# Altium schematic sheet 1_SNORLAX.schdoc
size 429 x 307 mm; Symbol: Drawing-Symbol_A4; Device: Drawing-Symbol_A4; @Project Name: Slowpoke_Adapter; @Page Count: 1; @Update Date: 2025-12-10; @Create Date: 2025-11-02; @Schematic Name: Schematic3; @Page No: 1; @Page Name: SNORLAX; Company: EasyEDA.com; Version: V1.0; Page Size: A4; @Create Time: 12:35:37; @Update Time: 15:02:42; Width: 1655; Height: 1170; Region Start: 1; X Region Count: 6; Y Region Count: 4; Blade Width: 10; Title Block Position: 3; @Board Name: SNORLAX
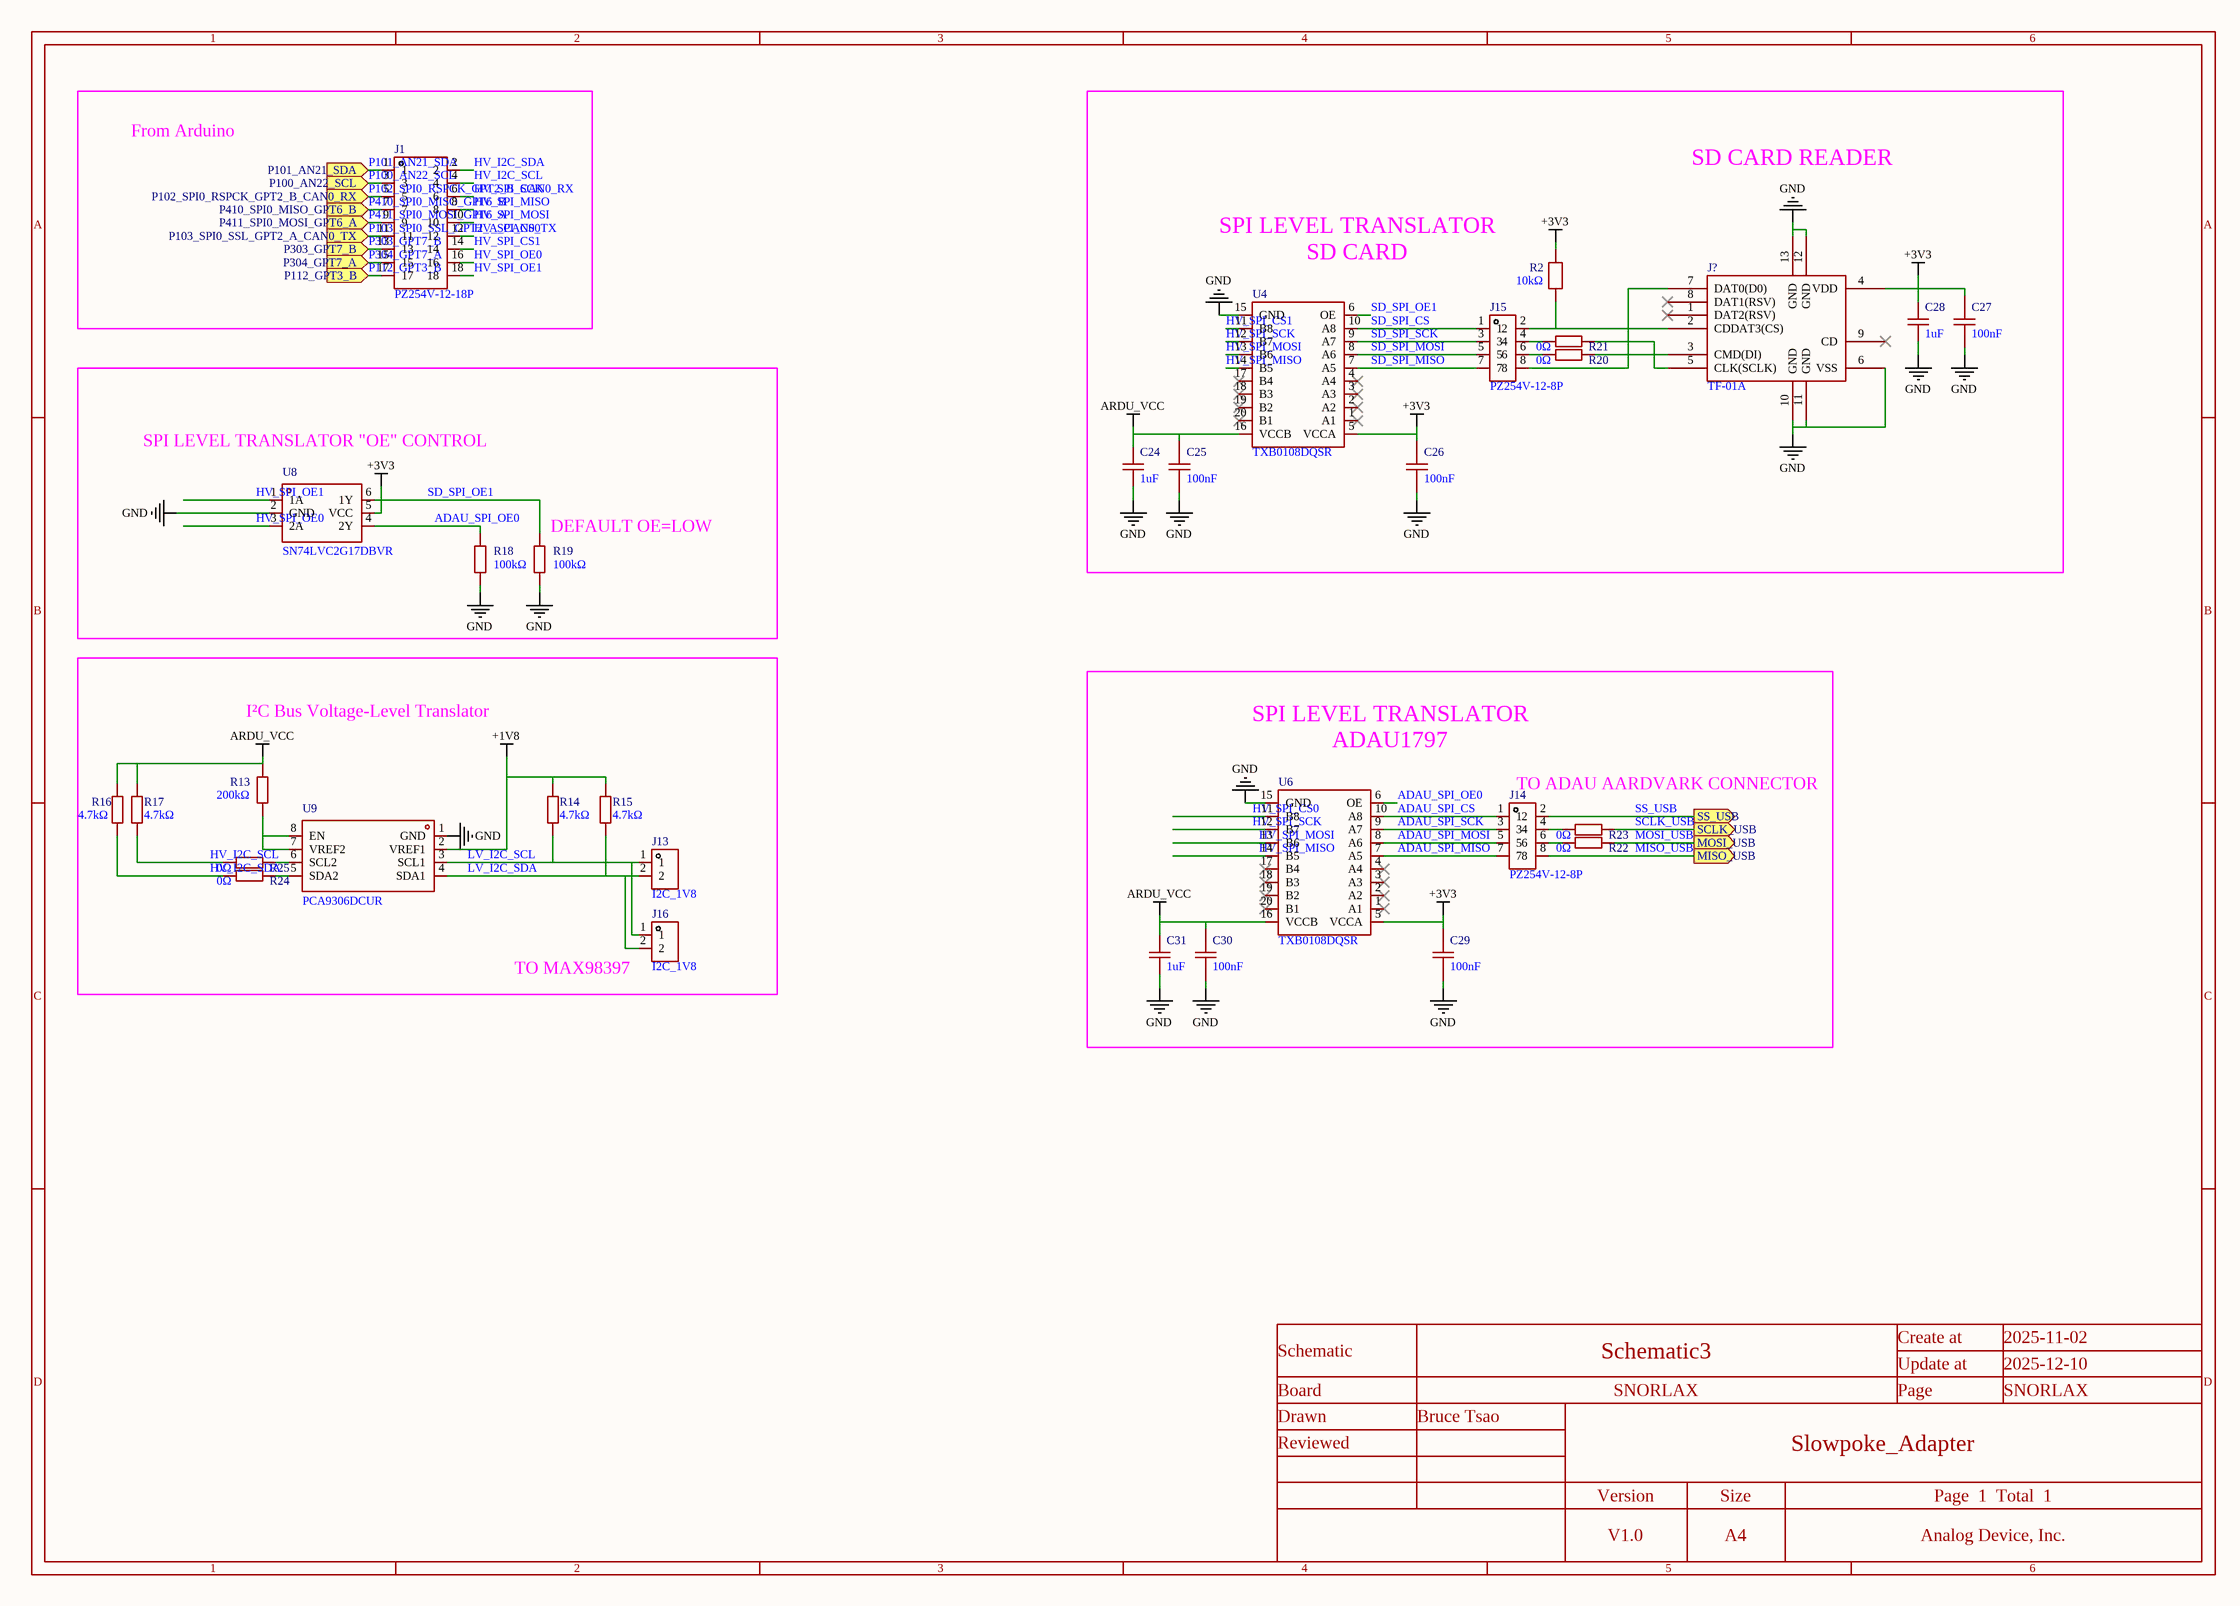
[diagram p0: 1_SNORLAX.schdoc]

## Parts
C24  1uF  [C0402]
C25  100nF  [C0402]
C26  100nF  [C0402]
C27  100nF  [C0402]
C28  1uF  [C0402]
C29  100nF  [C0402]
C30  100nF  [C0402]
C31  1uF  [C0402]
J1  PZ254V-12-18P  [HDR-TH_18P-P2.54-V-M-R2-C9-S2.54]
J13  I2C_1V8  [HDR-TH_2P-P2.54-V-M]
J14  PZ254V-12-8P  [HDR-TH_8P-P2.54-V-M-R2-C4-S2.54]
J15  PZ254V-12-8P  [HDR-TH_8P-P2.54-V-M-R2-C4-S2.54]
J16  I2C_1V8  [HDR-TH_2P-P2.54-V-M]
J?  TF-01A  [TF-SMD_TF-01A]
R2  10kΩ  [R0402]
R13  200kΩ  [R0603]
R14  4.7kΩ  [R0603]
R15  4.7kΩ  [R0603]
R16  4.7kΩ  [R0603]
R17  4.7kΩ  [R0603]
R18  100kΩ  [R0603]
R19  100kΩ  [R0603]
R20  0Ω  [R0402]
R21  0Ω  [R0402]
R22  0Ω  [R0402]
R23  0Ω  [R0402]
R24  0Ω  [R0402]
R25  0Ω  [R0402]
U4  TXB0108DQSR  [SON-20_L4.0-W2.0-P0.40-BL]
U6  TXB0108DQSR  [SON-20_L4.0-W2.0-P0.40-BL]
U8  SN74LVC2G17DBVR  [SOT-23-6_L2.9-W1.6-P0.95-LS2.8-BL]
U9  PCA9306DCUR  [SSOP-8_L2.0-W2.3-P0.50-LS3.1-BR]

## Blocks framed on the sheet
From Arduino: J1
SD CARD READER: C24-C28 J15 J? R2 R20 R21 U4
TO ADAU AARDVARK CONNECTOR: C29-C31 J14 R22 R23 U6

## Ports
MISO_USB (out), MOSI_USB (out), P100_AN22_SCL (in), P101_AN21_SDA (in), P102_SPI0_RSPCK_GPT2_B_CAN0_RX (in), P103_SPI0_SSL_GPT2_A_CAN0_TX (in), P112_GPT3_B (in), P303_GPT7_B (in), P304_GPT7_A (in), P410_SPI0_MISO_GPT6_B (in), P411_SPI0_MOSI_GPT6_A (in), SCLK_USB (out), SS_USB (out)

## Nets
+1V8: R14.2 R15.2 U9.2(VREF1)
+3V3: C26.2 C27.2 C28.2 C29.2 J?.4(VDD) R2.2 U4.5(VCCA) U6.5(VCCA) U8.5(VCC)
ARDU_VCC: C24.2 C25.2 C30.2 C31.2 R13.2 R16.2 R17.2 U4.16(VCCB) U6.16(VCCB)
GND: C24.1 C25.1 C26.1 C27.1 C28.1 C29.1 C30.1 C31.1 J?.6(VSS) J?.10(GND) J?.11(GND) J?.12(GND) J?.13(GND) R18.1 R19.1 U4.15(GND) U6.15(GND) U8.2(GND) U9.1(GND)
ADAU_SPI_CS: J14.1 U6.10(A8)
ADAU_SPI_MISO: J14.7 U6.7(A5)
ADAU_SPI_MOSI: J14.5 U6.8(A6)
ADAU_SPI_OE0: R18.2 U6.6(OE) U8.4(2Y)
ADAU_SPI_SCK: J14.3 U6.9(A7)
HV_I2C_SCL: J1.4 R17.1 R25.1
HV_I2C_SDA: J1.2 R16.1 R24.1
HV_SPI_CS0: J1.12 U6.11(B8)
HV_SPI_CS1: J1.14 U4.11(B8)
HV_SPI_MISO: J1.8 U4.14(B5) U6.14(B5)
HV_SPI_MOSI: J1.10 U4.13(B6) U6.13(B6)
HV_SPI_OE0: J1.16 U8.3(2A)
HV_SPI_OE1: J1.18 U8.1(1A)
HV_SPI_SCK: J1.6 U4.12(B7) U6.12(B7)
LV_I2C_SCL: J13.1 J16.1 R14.1 U9.3(SCL1)
LV_I2C_SDA: J13.2 J16.2 R15.1 U9.4(SDA1)
MISO_USB: J14.8 ; port MISO_USB
MOSI_USB: R22.2 ; port MOSI_USB
P100_AN22_SCL: J1.3 ; port P100_AN22_SCL
P101_AN21_SDA: J1.1 ; port P101_AN21_SDA
P102_SPI0_RSPCK_GPT2_B_CAN0_RX: J1.5 ; port P102_SPI0_RSPCK_GPT2_B_CAN0_RX
P103_SPI0_SSL_GPT2_A_CAN0_TX: J1.11 ; port P103_SPI0_SSL_GPT2_A_CAN0_TX
P112_GPT3_B: J1.17 ; port P112_GPT3_B
P303_GPT7_B: J1.13 ; port P303_GPT7_B
P304_GPT7_A: J1.15 ; port P304_GPT7_A
P410_SPI0_MISO_GPT6_B: J1.7 ; port P410_SPI0_MISO_GPT6_B
P411_SPI0_MOSI_GPT6_A: J1.9 ; port P411_SPI0_MOSI_GPT6_A
SCLK_USB: R23.2 ; port SCLK_USB
SD_SPI_CS: J15.1 U4.10(A8)
SD_SPI_MISO: J15.7 U4.7(A5)
SD_SPI_MOSI: J15.5 U4.8(A6)
SD_SPI_OE1: R19.2 U4.6(OE) U8.6(1Y)
SD_SPI_SCK: J15.3 U4.9(A7)
SS_USB: J14.2 ; port SS_USB
NetJ14_4: J14.4 R23.1
NetJ14_6: J14.6 R22.1
NetJ15_2: J15.2 J15.8 J?.2(CDDAT3(CS)) J?.7(DAT0(D0)) R2.1
NetJ15_4: J15.4 R21.1
NetJ15_6: J15.6 R20.1
NetJ?_3: J?.3(CMD(DI)) R20.2
NetJ?_5: J?.5(CLK(SCLK)) R21.2
NetR13_1: R13.1 U9.7(VREF2) U9.8(EN)
NetR24_2: R24.2 U9.5(SDA2)
NetR25_2: R25.2 U9.6(SCL2)

Not connected (* = marked no-connect by the designer): J? 1(DAT2(RSV))* 8(DAT1(RSV))* 9(CD)*; U4 1(A1)* 2(A2)* 3(A3)* 4(A4)* 17(B4)* 18(B3)* 19(B2)* 20(B1)*; U6 1(A1)* 2(A2)* 3(A3)* 4(A4)* 17(B4)* 18(B3)* 19(B2)* 20(B1)*

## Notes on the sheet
- (near U4) SPI LEVEL TRANSLATOR
  SD CARD
- (near U8) SPI LEVEL TRANSLATOR "OE" CONTROL
- (near R19) DEFAULT OE=LOW
- I²C Bus Voltage-Level Translator
- (near U6) SPI LEVEL TRANSLATOR
  ADAU1797
- (near J16) TO MAX98397

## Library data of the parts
C24 C28 C31 = CL05A105KP5NNNC: Manufacturer: SAMSUNG(三星); Add into BOM: yes; Tolerance: ±10%; Voltage Rating: 10V; Temperature Coefficient: X5R
C25-C27 C29 C30 = GRM155R61H104KE19D: Manufacturer: muRata(村田); Add into BOM: yes; Tolerance: ±10%
J1 = PZ254V-12-18P: Manufacturer: XFCN(兴飞); Add into BOM: yes; Pin Structure: 2x9P; Pitch: 2.54mm; Circluar Pins/Square Pins: Pin Header
J13 J16 = PZ254V-11-02P: Manufacturer: XFCN(兴飞); Add into BOM: yes; Pin Structure: 1x2P; Pitch: 2.54mm; Circluar Pins/Square Pins: Pin Header
J14 J15 = PZ254V-12-8P: Manufacturer: XFCN(兴飞); Add into BOM: yes; Pin Structure: 2x4P; Pitch: 2.54mm; Circluar Pins/Square Pins: Pin Header
J? = TF-01A_C91145: Manufacturer: 韩国韩荣; Add into BOM: yes; Card Connection Mode: Push-Push; Card Type: MicroSD Card (TF Card); Connector Type: Connector and Ejector; Supplementary Features: With Locating Post
R2 = HP02WAF1002TCE: Manufacturer: UNI-ROYAL(厚声); Add into BOM: yes; Tolerance: ±1%; Power(Watts): 100mW; Voltage-Supply(Max): 50V; Temperature Coefficient: ±100ppm/℃
R13 = 0603WAF2003T5E: Manufacturer: UNI-ROYAL(厚声); Add into BOM: yes; Tolerance: ±1%; Temperature Coefficient: ±100ppm/℃
R14-R17 = 0603WAF4701T5E: Manufacturer: UNI-ROYAL(厚声); Add into BOM: yes; Tolerance: ±1%; Power(Watts): 100mW; Voltage-Supply(Max): 75V; Temperature Coefficient: ±100ppm/℃
R18 R19 = 0603WAF1003T5E: Manufacturer: UNI-ROYAL(厚声); Add into BOM: yes; Tolerance: ±1%; Power(Watts): 100mW; Voltage-Supply(Max): 75V; Temperature Coefficient: ±100ppm/℃
R20-R25 = 0402WGJ0000TCE: Manufacturer: UNI-ROYAL(厚声); Add into BOM: yes; Tolerance: ±5%
U4 U6 = TXB0108DQSR: Manufacturer: TI(德州仪器); Add into BOM: yes
U8 = SN74LVC2G17DBVR: Manufacturer: TI(德州仪器); Add into BOM: yes; Input type: Schmitt Trigger; Voltage - Supply: 1.65V~5.5V; Number of Elements: 2; Number of Bits per Element: 1; Current - Output Low(IOL): 32mA; Logic Family: 74LVC
U9 = PCA9306DCUR: Manufacturer: TI(德州仪器); Add into BOM: yes; Channel Type: Bidirectional; Voltage - Supply(VCCA): 1.2V~3.3V; Voltage - Supply(VCCB): 1.8V~5.5V; Number of Circuits: 2; Output Type: Open Drain；Push-pull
